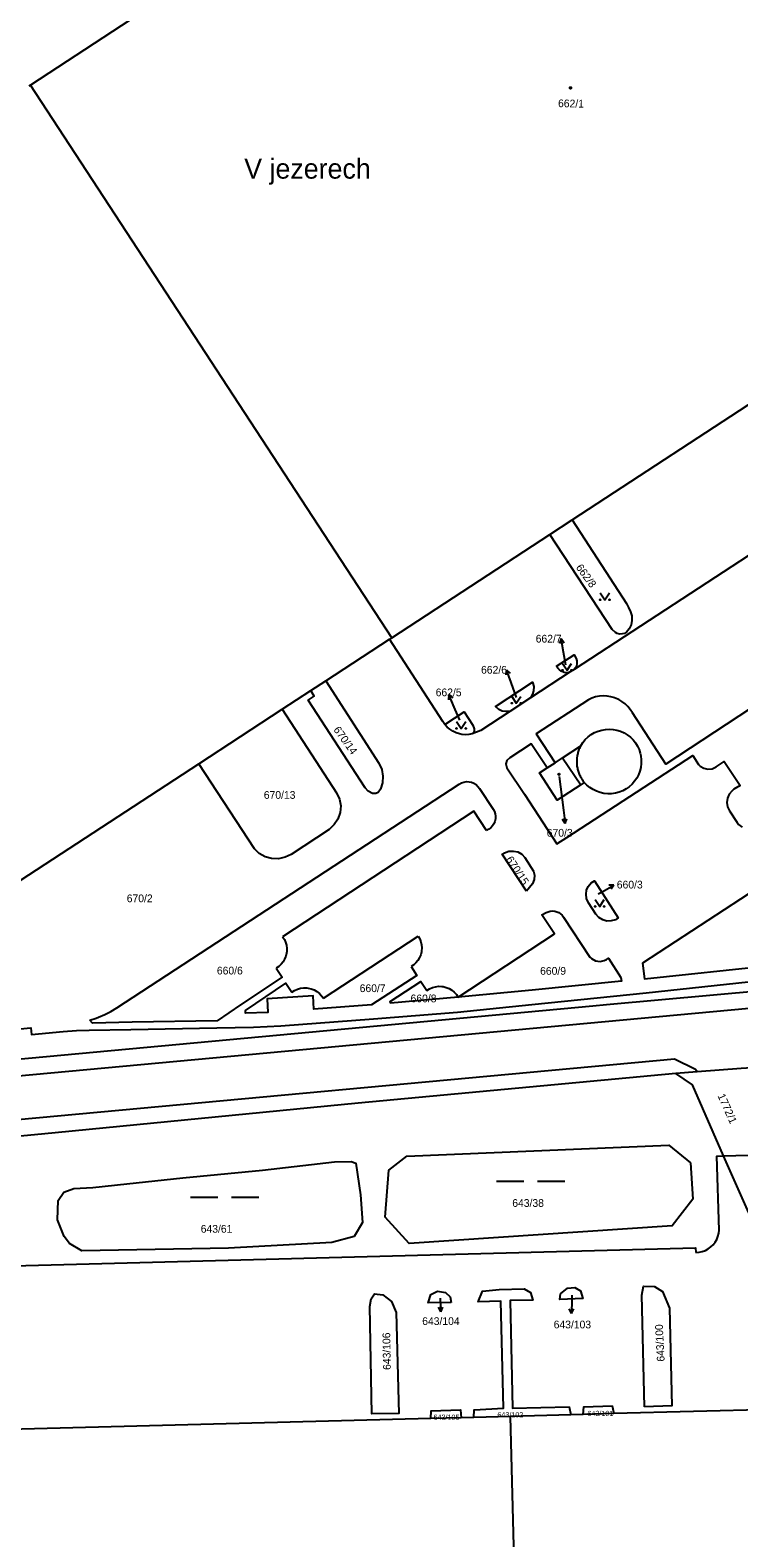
# Model space of a CAD drawing. Extents: x -724107 to -720612, y -1045267 to -1038441.
# Drawn here: x -723392.9 to -723237.1, y -1041570.2 to -1041238.7 of the extents above; entities that cross this region are included whole.
import ezdxf

# ---------------------------------------------------------------- set-up
doc = ezdxf.new("R2010")
doc.units = 0
for name, color, linetype in [('Hranice parcel', 7, 'Continuous'), ('Parcelní čísla', 7, 'Continuous'), ('Pop  PČ popisy', 7, 'Continuous'), ('Vnitřní kresba', 7, 'Continuous'), ('Značky budov', 7, 'Continuous'), ('Značky kultur', 7, 'Continuous')]:
    doc.layers.add(name, color=color, linetype=linetype)

msp = doc.modelspace()

# ---------------------------------------------------------------- linework, layer by layer
at = {"layer": 'Hranice parcel'}
for p, q in [((-723358.07, -1041228.07), (-723392.8, -1041250.79)), ((-723392.8, -1041250.79), (-723393.16, -1041251.03)), ((-723313.41, -1041372.3), (-723392.8, -1041250.79)), ((-723273.73, -1041346.35), (-723159.1, -1041271.4)), ((-723144.51, -1041295.05), (-723273.33, -1041379.25)), ((-723278.67, -1041349.58), (-723273.73, -1041346.35)), ((-723313.41, -1041372.3), (-723278.67, -1041349.58)), ((-723327.91, -1041381.78), (-723313.88, -1041372.61)), ((-723313.88, -1041372.61), (-723313.41, -1041372.3)), ((-723302.16, -1041390.71), (-723313.88, -1041372.61)), ((-723331.16, -1041383.9), (-723327.91, -1041381.78)), ((-723274.16, -1041379.8), (-723282.93, -1041385.53)), ((-723273.33, -1041379.25), (-723274.16, -1041379.8)), ((-723337.47, -1041388.02), (-723331.16, -1041383.9)), ((-723355.8, -1041399.99), (-723337.47, -1041388.02)), ((-723287.47, -1041388.5), (-723293.84, -1041392.66)), ((-723282.93, -1041385.53), (-723287.47, -1041388.5)), ((-723301.72, -1041391.35), (-723302.16, -1041390.71)), ((-723293.84, -1041392.66), (-723295.69, -1041393.44)), ((-723403.1, -1041430.88), (-723355.8, -1041399.99)), ((-723279.25, -1041400.91), (-723277.51, -1041399.76)), ((-723373.83, -1041453.66), (-723298.55, -1041404.46)), ((-723294.13, -1041405.43), (-723291.12, -1041409.98)), ((-723328.41, -1041451.55), (-723307.58, -1041437.91)), ((-723240.46, -1041486.18), (-723228.37, -1041485.87)), ((-723216.03, -1041541.55), (-723240.46, -1041486.18)), ((-723304.83, -1041543.93), (-723425.25, -1041547.09)), ((-723298.13, -1041543.75), (-723304.83, -1041543.93)), ((-723295.39, -1041543.68), (-723298.13, -1041543.75)), ((-723287.32, -1041543.47), (-723295.39, -1041543.68)), ((-723274.07, -1041543.11), (-723287.32, -1041543.47)), ((-723283.25, -1041700.45), (-723287.32, -1041543.47)), ((-723271.36, -1041543.04), (-723274.07, -1041543.11)), ((-723264.63, -1041542.86), (-723271.36, -1041543.04)), ((-723216.03, -1041541.55), (-723264.63, -1041542.86))]:
    msp.add_line(p, q, dxfattribs=at)
for points in [[(-723136.93, -1041298.82), (-723137.65, -1041299.68), (-723138.62, -1041300.82), (-723139.23, -1041301.61), (-723140.04, -1041302.87), (-723140.83, -1041304.16), (-723141.3, -1041305.03), (-723141.69, -1041305.94), (-723141.98, -1041306.89), (-723142.18, -1041307.86), (-723142.26, -1041308.35), (-723142.25, -1041309.33), (-723142.15, -1041310.32), (-723142.02, -1041311.3), (-723141.74, -1041312.25), (-723141.21, -1041313.64), (-723140.75, -1041314.54), (-723140.23, -1041315.38), (-723135.22, -1041322.83), (-723197.32, -1041363.4), (-723253.15, -1041400.11), (-723260.51, -1041388.79)], [(-723273.73, -1041346.35), (-723261.82, -1041364.8), (-723261.34, -1041365.65), (-723260.9, -1041366.56), (-723260.65, -1041367.5), (-723260.64, -1041368.49), (-723260.81, -1041369.44), (-723261.2, -1041370.32), (-723261.83, -1041371.05), (-723262.22, -1041371.33), (-723262.68, -1041371.46), (-723263.37, -1041371.51), (-723263.83, -1041371.38), (-723264.26, -1041371.13), (-723264.93, -1041370.45), (-723278.67, -1041349.58)], [(-723274.16, -1041379.8), (-723274.6, -1041379.99), (-723275.52, -1041379.92), (-723276.19, -1041379.64), (-723276.56, -1041379.36), (-723276.9, -1041379.01), (-723277.16, -1041378.57), (-723273.31, -1041376.07), (-723272.85, -1041376.88), (-723272.71, -1041377.35), (-723272.71, -1041378.04), (-723272.81, -1041378.5), (-723273.01, -1041378.92), (-723273.33, -1041379.25)], [(-723327.91, -1041381.78), (-723316.2, -1041399.85), (-723315.58, -1041401.23), (-723315.32, -1041402.71), (-723315.44, -1041404.19), (-723315.88, -1041405.6), (-723316.35, -1041406.28), (-723316.89, -1041406.56), (-723317.66, -1041406.5), (-723318.56, -1041406.04), (-723319.25, -1041405.32), (-723331.78, -1041386.05), (-723330.43, -1041385.15), (-723331.16, -1041383.9)], [(-723287.47, -1041388.5), (-723288.25, -1041388.53), (-723289.16, -1041388.41), (-723289.9, -1041388.08), (-723290.62, -1041387.42), (-723282.49, -1041382.07), (-723282.16, -1041382.98), (-723282.25, -1041383.93), (-723282.49, -1041384.73), (-723282.93, -1041385.53)], [(-723260.51, -1041388.79), (-723260.97, -1041388.07), (-723261.51, -1041387.42), (-723262.12, -1041386.83), (-723262.8, -1041386.31), (-723263.53, -1041385.88), (-723264.31, -1041385.54), (-723264.4, -1041385.51), (-723265.22, -1041385.27), (-723266.06, -1041385.13), (-723266.91, -1041385.09), (-723267.76, -1041385.15), (-723268.59, -1041385.31), (-723269.4, -1041385.56), (-723270.18, -1041385.91)], [(-723337.47, -1041388.02), (-723325.53, -1041406.41), (-723324.87, -1041407.78), (-723324.61, -1041409.25), (-723324.76, -1041410.72), (-723325.25, -1041412.18), (-723326.05, -1041413.37), (-723327.12, -1041414.42), (-723335.51, -1041419.91), (-723336.83, -1041420.55), (-723338.28, -1041420.92), (-723339.8, -1041420.84), (-723341.24, -1041420.47), (-723342.54, -1041419.7), (-723343.58, -1041418.67), (-723355.8, -1041399.99)], [(-723301.72, -1041391.35), (-723297.46, -1041388.61), (-723295.56, -1041391.54), (-723295.28, -1041392.3), (-723295.25, -1041392.74), (-723295.33, -1041393.04), (-723295.69, -1041393.44)], [(-723270.18, -1041385.91), (-723281.68, -1041393.43), (-723277.51, -1041399.76)], [(-723295.69, -1041393.44), (-723296.45, -1041393.57), (-723297.22, -1041393.6), (-723297.99, -1041393.53), (-723298.53, -1041393.41), (-723299.27, -1041393.17), (-723299.96, -1041392.84), (-723300.61, -1041392.42), (-723301.2, -1041391.92), (-723301.72, -1041391.35)], [(-723271.85, -1041396.02), (-723271.4, -1041395.31), (-723270.86, -1041394.66), (-723270.25, -1041394.08), (-723269.58, -1041393.57), (-723268.85, -1041393.15), (-723268.07, -1041392.82), (-723267.26, -1041392.58), (-723266.43, -1041392.43), (-723265.59, -1041392.39), (-723264.75, -1041392.45), (-723263.92, -1041392.6), (-723263.12, -1041392.86), (-723262.35, -1041393.21), (-723261.63, -1041393.64), (-723260.96, -1041394.16), (-723260.36, -1041394.75), (-723259.84, -1041395.41), (-723259.4, -1041396.13), (-723259.04, -1041396.89), (-723258.78, -1041397.7), (-723258.66, -1041398.28), (-723258.56, -1041399.12), (-723258.57, -1041399.96), (-723258.67, -1041400.8), (-723258.87, -1041401.62), (-723259.17, -1041402.4), (-723259.56, -1041403.15), (-723260.04, -1041403.85), (-723260.59, -1041404.48), (-723261.22, -1041405.05), (-723261.91, -1041405.53), (-723262.65, -1041405.93), (-723263.43, -1041406.24), (-723264.25, -1041406.46), (-723265.08, -1041406.58), (-723265.93, -1041406.59), (-723266.76, -1041406.51), (-723267.59, -1041406.33), (-723268.38, -1041406.05), (-723269.14, -1041405.68), (-723269.85, -1041405.23), (-723270.5, -1041404.69), (-723271.08, -1041404.08)], [(-723279.25, -1041400.91), (-723282.76, -1041395.62), (-723287.46, -1041398.72), (-723288.12, -1041399.3), (-723288.31, -1041400.03), (-723288.1, -1041400.88), (-723284.26, -1041406.7), (-723277.14, -1041417.56), (-723274.93, -1041416.2), (-723247.26, -1041398.18), (-723245.96, -1041400.18), (-723245.64, -1041400.51), (-723244.8, -1041400.97), (-723243.96, -1041401.21), (-723243, -1041401.11), (-723242.1, -1041400.67), (-723240.34, -1041399.51), (-723236.82, -1041404.74), (-723238.21, -1041405.61), (-723238.62, -1041405.94), (-723239.22, -1041406.69), (-723239.59, -1041407.54), (-723239.74, -1041408.49), (-723239.62, -1041409.46), (-723239.21, -1041410.32), (-723237.49, -1041412.93), (-723237.19, -1041413.32), (-723236.41, -1041413.9)], [(-723277.51, -1041399.76), (-723275.85, -1041398.66), (-723271.85, -1041396.02)], [(-723271.08, -1041404.08), (-723271.87, -1041404.6), (-723277.03, -1041407.98), (-723280.92, -1041402.01), (-723279.25, -1041400.91)], [(-723298.55, -1041404.46), (-723298.06, -1041404.19), (-723297.53, -1041404.01), (-723296.98, -1041403.93), (-723296.42, -1041403.95), (-723296.39, -1041403.95), (-723295.85, -1041404.07), (-723295.33, -1041404.29), (-723294.86, -1041404.59), (-723294.46, -1041404.98), (-723294.13, -1041405.43)], [(-723292.56, -1041414.63), (-723295.33, -1041410.43), (-723337.37, -1041438.03)], [(-723291.12, -1041409.98), (-723290.85, -1041410.47), (-723290.67, -1041410.99), (-723290.58, -1041411.55), (-723290.6, -1041412.1), (-723290.72, -1041412.66), (-723290.93, -1041413.17), (-723291.23, -1041413.64), (-723291.61, -1041414.05), (-723292.06, -1041414.38), (-723292.56, -1041414.63)], [(-723283.79, -1041427.99), (-723289.14, -1041419.84), (-723288.6, -1041419.55), (-723287.67, -1041419.23), (-723286.65, -1041419.18), (-723285.66, -1041419.33), (-723284.82, -1041419.86), (-723284.17, -1041420.6), (-723282.26, -1041423.57), (-723282.01, -1041424.48), (-723282.11, -1041425.47), (-723282.46, -1041426.4), (-723283.79, -1041427.99)], [(-723229.56, -1041425.09), (-723258.26, -1041443.86), (-723257.88, -1041447.24), (-723230.21, -1041444.32)], [(-723265.17, -1041434.53), (-723266.13, -1041434.6), (-723267.04, -1041434.3), (-723267.88, -1041433.82), (-723268.56, -1041433.08), (-723270.19, -1041430.58), (-723270.58, -1041429.63), (-723270.69, -1041428.65), (-723270.58, -1041427.77), (-723270.2, -1041426.96), (-723269.57, -1041426.19), (-723268.87, -1041425.71), (-723263.65, -1041433.9), (-723264.23, -1041434.27), (-723265.17, -1041434.53)], [(-723298.78, -1041451.27), (-723277.64, -1041437.38), (-723280.39, -1041433.24), (-723279.44, -1041432.67), (-723278.55, -1041432.39), (-723278.04, -1041432.36), (-723277.59, -1041432.4), (-723277.12, -1041432.53), (-723276.71, -1041432.71), (-723276.28, -1041432.99), (-723275.95, -1041433.29), (-723275.66, -1041433.7), (-723269.85, -1041442.49), (-723269.49, -1041442.83), (-723268.61, -1041443.34), (-723267.63, -1041443.45), (-723266.7, -1041443.27), (-723266.2, -1041443.04), (-723265.76, -1041442.76), (-723263.05, -1041447), (-723262.92, -1041447.78), (-723282.56, -1041449.78), (-723298.78, -1041451.27)], [(-723337.37, -1041438.03), (-723337, -1041438.61), (-723336.72, -1041439.23), (-723336.53, -1041439.89), (-723336.44, -1041440.57), (-723336.45, -1041441.25), (-723336.5, -1041441.65), (-723336.66, -1041442.32), (-723336.93, -1041442.95), (-723337.28, -1041443.54), (-723337.71, -1041444.07), (-723338.21, -1041444.54), (-723338.78, -1041444.92)], [(-723307.58, -1041437.91), (-723307.24, -1041438.5), (-723306.99, -1041439.14), (-723306.84, -1041439.81), (-723306.79, -1041440.49), (-723306.83, -1041441.17), (-723306.85, -1041441.33), (-723307.02, -1041441.99), (-723307.28, -1041442.62), (-723307.63, -1041443.21), (-723308.07, -1041443.74), (-723308.57, -1041444.2), (-723309.14, -1041444.58)], [(-723338.78, -1041444.92), (-723337.5, -1041446.88), (-723346.65, -1041453.01), (-723351.77, -1041456.47), (-723370.44, -1041456.81), (-723379.13, -1041456.99), (-723379.76, -1041456.38)], [(-723309.14, -1041444.58), (-723307.85, -1041446.54), (-723317.82, -1041453), (-723330.53, -1041453.95), (-723330.7, -1041450.99), (-723340.75, -1041451.7), (-723340.61, -1041454.66), (-723345.56, -1041454.85), (-723345.57, -1041454.2), (-723336.64, -1041448.19), (-723335.34, -1041450.17)], [(-723596.71, -1041477.01), (-723494.2, -1041467.47), (-723392.69, -1041458.04), (-723392.57, -1041459.49), (-723385.62, -1041458.84), (-723382.67, -1041458.65), (-723379.91, -1041458.57), (-723370.76, -1041458.42), (-723351.84, -1041458.07), (-723343.77, -1041457.88), (-723337.79, -1041457.62), (-723317.38, -1041456.05), (-723298.97, -1041454.59), (-723282.65, -1041452.9), (-723257.49, -1041450.34), (-723232.35, -1041447.66), (-723231.52, -1041447.79), (-723231.37, -1041449.81)], [(-723298.78, -1041451.27), (-723313.69, -1041452.65), (-723313.74, -1041452.25), (-723306.98, -1041447.86), (-723305.69, -1041449.81)], [(-723231.37, -1041449.81), (-723266.2, -1041452.99), (-723269.24, -1041453.27), (-723476.99, -1041472.53), (-723481.56, -1041473.15), (-723735.68, -1041496.18)], [(-723335.34, -1041450.17), (-723334.75, -1041449.81), (-723334.11, -1041449.53), (-723333.44, -1041449.35), (-723332.75, -1041449.26), (-723332.06, -1041449.28), (-723331.78, -1041449.31), (-723331.1, -1041449.47), (-723330.45, -1041449.72), (-723329.85, -1041450.06), (-723329.3, -1041450.49), (-723328.82, -1041450.99), (-723328.41, -1041451.55)], [(-723305.69, -1041449.81), (-723305.1, -1041449.45), (-723304.46, -1041449.18), (-723303.79, -1041449), (-723303.1, -1041448.92), (-723302.41, -1041448.94), (-723302.1, -1041448.99), (-723301.43, -1041449.15), (-723300.79, -1041449.41), (-723300.19, -1041449.76), (-723299.65, -1041450.2), (-723299.17, -1041450.7), (-723298.78, -1041451.27)], [(-723379.76, -1041456.38), (-723378.32, -1041455.9), (-723377.86, -1041455.73), (-723376.47, -1041455.13), (-723375.13, -1041454.44), (-723373.83, -1041453.66)], [(-723250.95, -1041468.05), (-723320.79, -1041474.6), (-723390.39, -1041481.44), (-723449.81, -1041487.09), (-723486.96, -1041490.42)], [(-723234.24, -1041466.83), (-723236.59, -1041467), (-723246.27, -1041467.71), (-723250.95, -1041468.05)], [(-723240.46, -1041486.18), (-723247.34, -1041470.58), (-723250.95, -1041468.05)], [(-723247.75, -1041487.71), (-723247.24, -1041495.69), (-723251.77, -1041501.56), (-723309.6, -1041505.45), (-723314.83, -1041499.68), (-723314.05, -1041489.35), (-723310.05, -1041486.29), (-723252.53, -1041483.82), (-723247.75, -1041487.71)], [(-723319.83, -1041500.86), (-723321.64, -1041503.88), (-723326.57, -1041505.2), (-723349.3, -1041506.47), (-723381.47, -1041507.05), (-723384.18, -1041505.44), (-723385.4, -1041503.95), (-723386.82, -1041500.24), (-723386.72, -1041496), (-723385.49, -1041494.15), (-723383.27, -1041493.34), (-723379.11, -1041493.16), (-723371.59, -1041492.35), (-723359.28, -1041491.05), (-723341.83, -1041489.34), (-723325.99, -1041487.48), (-723322.3, -1041487.43), (-723321.31, -1041487.82), (-723320.24, -1041494.74), (-723319.83, -1041500.86)], [(-723241.47, -1041502.49), (-723241.97, -1041486.22), (-723240.46, -1041486.18)], [(-723246.56, -1041507.4), (-723245.85, -1041507.35), (-723245.15, -1041507.2), (-723244.48, -1041506.96), (-723243.85, -1041506.62), (-723243.31, -1041506.22), (-723242.79, -1041505.73), (-723242.35, -1041505.17), (-723241.99, -1041504.55), (-723241.72, -1041503.89), (-723241.55, -1041503.2), (-723241.47, -1041502.49)], [(-723663.68, -1041518.32), (-723546.71, -1041515.26), (-723488.28, -1041513.72), (-723488.3, -1041512.78), (-723346.58, -1041509.03), (-723246.63, -1041506.39), (-723246.56, -1041507.4)], [(-723312.39, -1041520.59), (-723311.81, -1041542.81), (-723317.78, -1041542.93), (-723318.23, -1041519.29), (-723317.92, -1041517.62), (-723317.17, -1041516.52), (-723315.36, -1041516.71), (-723313.45, -1041518.2), (-723312.39, -1041520.59)], [(-723300.34, -1041518.42), (-723305.43, -1041518.5), (-723304.8, -1041516.64), (-723303.36, -1041515.94), (-723301.57, -1041516.19), (-723300.58, -1041517.19), (-723300.34, -1041518.42)], [(-723295.39, -1041543.68), (-723295.26, -1041541.99), (-723288.85, -1041541.68), (-723289.39, -1041518.11), (-723294.4, -1041518.27), (-723293.44, -1041515.95), (-723289.8, -1041515.59), (-723284.27, -1041515.45), (-723282.94, -1041516.26), (-723282.42, -1041517.94), (-723287.4, -1041518.01), (-723286.87, -1041541.63), (-723274.38, -1041541.39), (-723274.07, -1041543.11)], [(-723276.35, -1041516.55), (-723274.79, -1041515.26), (-723273.18, -1041515.16), (-723271.93, -1041515.88), (-723271.4, -1041517.56), (-723276.43, -1041517.74), (-723276.35, -1041516.55)], [(-723257.85, -1041541.34), (-723258.45, -1041516.83), (-723258.05, -1041514.84), (-723255.65, -1041514.91), (-723253.91, -1041516), (-723252.37, -1041519.67), (-723251.87, -1041541.17), (-723257.85, -1041541.34)], [(-723271.36, -1041543.04), (-723271.17, -1041541.33), (-723264.93, -1041541.15), (-723264.63, -1041542.86)], [(-723304.83, -1041543.93), (-723304.7, -1041542.27), (-723298.32, -1041542.04), (-723298.13, -1041543.75)]]:
    msp.add_lwpolyline(points, dxfattribs=at)
at = {"layer": 'Pop  PČ popisy'}
for p, q in [((-723276.18, -1041372.49), (-723276.5, -1041373.57)), ((-723275.66, -1041375.45), (-723276.18, -1041372.49)), ((-723276.18, -1041372.49), (-723275.51, -1041373.39)), ((-723275.13, -1041378.33), (-723275.66, -1041375.45)), ((-723288.21, -1041379.33), (-723288.33, -1041380.44)), ((-723287.18, -1041382.15), (-723288.21, -1041379.33)), ((-723288.21, -1041379.33), (-723287.39, -1041380.1)), ((-723285.97, -1041385.42), (-723287.18, -1041382.15)), ((-723300.85, -1041384.8), (-723300.92, -1041385.92)), ((-723299.68, -1041387.56), (-723300.85, -1041384.8)), ((-723300.85, -1041384.8), (-723300, -1041385.52)), ((-723298.47, -1041390.42), (-723299.68, -1041387.56)), ((-723276.6, -1041402.8), (-723275.65, -1041410.16)), ((-723275.65, -1041410.16), (-723275.28, -1041413.14)), ((-723275.28, -1041413.14), (-723275.9, -1041412.21)), ((-723275.28, -1041413.14), (-723274.91, -1041412.08)), ((-723268.06, -1041428.61), (-723267.18, -1041428.12)), ((-723267.18, -1041428.12), (-723264.56, -1041426.67)), ((-723264.56, -1041426.67), (-723265.67, -1041426.71)), ((-723264.56, -1041426.67), (-723265.19, -1041427.59)), ((-723302.73, -1041517.46), (-723302.62, -1041520.46)), ((-723273.85, -1041517.81), (-723273.9, -1041520.81)), ((-723273.83, -1041516.83), (-723273.85, -1041517.81)), ((-723302.62, -1041520.46), (-723303.16, -1041519.48)), ((-723302.62, -1041520.46), (-723302.16, -1041519.44)), ((-723273.9, -1041520.81), (-723274.39, -1041519.8)), ((-723273.9, -1041520.81), (-723273.38, -1041519.82))]:
    msp.add_line(p, q, dxfattribs=at)
at = {"layer": 'Vnitřní kresba'}
for p, q in [((-723275.85, -1041398.66), (-723271.87, -1041404.6)), ((-723251.24, -1041464.9), (-723450.16, -1041483.3)), ((-723246.63, -1041467.18), (-723251.24, -1041464.9)), ((-723246.27, -1041467.71), (-723246.63, -1041467.18))]:
    msp.add_line(p, q, dxfattribs=at)
for points in [[(-723271.85, -1041396.02), (-723271.96, -1041396.22), (-723272.07, -1041396.43), (-723272.16, -1041396.65), (-723272.25, -1041396.86), (-723272.33, -1041397.08), (-723272.41, -1041397.3), (-723272.48, -1041397.52), (-723272.54, -1041397.74), (-723272.59, -1041397.97), (-723272.64, -1041398.2), (-723272.68, -1041398.43), (-723272.71, -1041398.66), (-723272.73, -1041398.89), (-723272.75, -1041399.12), (-723272.76, -1041399.36), (-723272.76, -1041399.59), (-723272.75, -1041399.82), (-723272.74, -1041400.06), (-723272.72, -1041400.29), (-723272.69, -1041400.52), (-723272.65, -1041400.75), (-723272.6, -1041400.98), (-723272.55, -1041401.2), (-723272.49, -1041401.43), (-723272.43, -1041401.65), (-723272.35, -1041401.87), (-723272.27, -1041402.09), (-723272.18, -1041402.31), (-723272.08, -1041402.52), (-723271.98, -1041402.73), (-723271.87, -1041402.93), (-723271.76, -1041403.13), (-723271.63, -1041403.33), (-723271.51, -1041403.53), (-723271.37, -1041403.71), (-723271.23, -1041403.9), (-723271.08, -1041404.08)], [(-724063.89, -1041530.51), (-723156.58, -1041446.45), (-723150.6, -1041445.9), (-723118.1, -1041442.89)]]:
    msp.add_lwpolyline(points, dxfattribs=at)
at = {"layer": 'Značky budov'}
for centre in [(-723274.11, -1041251.42), (-723276.63, -1041402.32)]:
    msp.add_circle(centre, 0.175, dxfattribs=at)
at = {"layer": 'Značky kultur'}
for p, q in [((-723290.38, -1041491.74), (-723284.38, -1041491.74)), ((-723281.38, -1041491.74), (-723275.38, -1041491.74)), ((-723357.64, -1041495.29), (-723351.64, -1041495.29)), ((-723348.64, -1041495.29), (-723342.64, -1041495.29))]:
    msp.add_line(p, q, dxfattribs=at)
for points in [[(-723267.57, -1041362.43), (-723266.57, -1041363.93), (-723265.57, -1041362.43)], [(-723275.88, -1041377.95), (-723274.88, -1041379.45), (-723273.88, -1041377.95)], [(-723287.03, -1041385.18), (-723286.03, -1041386.68), (-723285.03, -1041385.18)], [(-723299.14, -1041390.71), (-723298.14, -1041392.21), (-723297.14, -1041390.71)], [(-723268.7, -1041429.85), (-723267.7, -1041431.35), (-723266.7, -1041429.85)]]:
    msp.add_lwpolyline(points, dxfattribs=at)
for centre in [(-723267.57, -1041363.93), (-723265.57, -1041363.93), (-723275.88, -1041379.45), (-723273.88, -1041379.45), (-723287.03, -1041386.68), (-723285.03, -1041386.68), (-723299.14, -1041392.21), (-723297.14, -1041392.21), (-723268.7, -1041431.35), (-723266.7, -1041431.35)]:
    msp.add_circle(centre, 0.1, dxfattribs=at)

# ---------------------------------------------------------------- texts
at = {"layer": 'Parcelní čísla'}
for s, rotation, p in [('662/1', 359, (-723276.86, -1041255.65)), ('662/8', 306, (-723273.02, -1041356.87)), ('670/14', 306, (-723326.3, -1041392.54)), ('670/15', 303, (-723288.37, -1041421)), ('1772/1', 294, (-723241.84, -1041472.96)), ('643/100', 93, (-723253.42, -1041531.38)), ('643/106', 91, (-723313.6, -1041533.23))]:
    msp.add_text(s, height=1.7, rotation=rotation, dxfattribs=at).set_placement(p)
for s, height, p in [('662/7', 1.7, (-723281.76, -1041373.35)), ('662/6', 1.7, (-723293.77, -1041380.19)), ('662/5', 1.7, (-723303.74, -1041385.15)), ('670/13', 1.7, (-723341.51, -1041407.7)), ('670/3', 1.7, (-723279.33, -1041416.02)), ('660/3', 1.7, (-723263.94, -1041427.41)), ('670/2', 1.7, (-723371.63, -1041430.43)), ('660/6', 1.7, (-723351.82, -1041446.31)), ('660/9', 1.7, (-723280.79, -1041446.38)), ('660/7', 1.7, (-723320.44, -1041450.19)), ('660/8', 1.7, (-723309.26, -1041452.43)), ('643/38', 1.7, (-723286.91, -1041497.4)), ('643/61', 1.7, (-723355.37, -1041503.08)), ('643/104', 1.7, (-723306.7, -1041523.37)), ('643/103', 1.7, (-723277.81, -1041524.11)), ('643/105', 1.139, (-723304.21, -1041544.21)), ('643/102', 1.139, (-723290.18, -1041543.67)), ('643/101', 1.139, (-723270.4, -1041543.38))]:
    msp.add_text(s, height=height, dxfattribs=at).set_placement(p)
at = {"layer": 'Pop  PČ popisy'}
msp.add_text('V jezerech', height=4.4, dxfattribs=at).set_placement((-723345.81, -1041271.37))

doc.saveas('drawing.dxf')
